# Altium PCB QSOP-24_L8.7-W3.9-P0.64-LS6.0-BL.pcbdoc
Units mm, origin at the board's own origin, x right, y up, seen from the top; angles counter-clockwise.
Board outline 21.81 x 19.48 mm, 2 copper layers (Top Layer, Bottom Layer), stack 0 mm thick; 1 components, 0 nets, 24 pads, 0 vias.
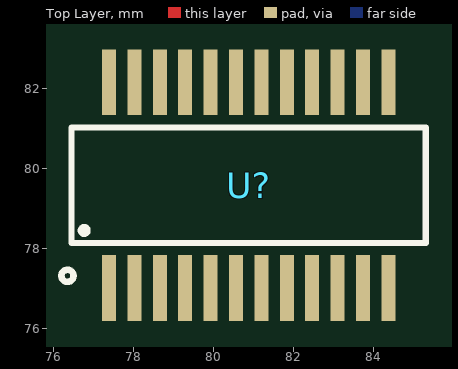
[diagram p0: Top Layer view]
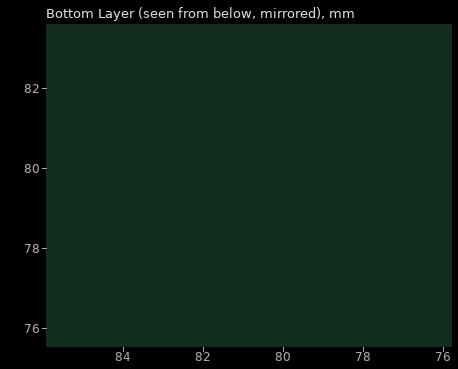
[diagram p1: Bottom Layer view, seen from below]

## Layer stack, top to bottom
Top Layer: signal copper (thickness not stored)
Bottom Layer: signal copper (thickness not stored)

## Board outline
91.659,69.85 69.85,69.85 69.85,89.33 91.659,89.33

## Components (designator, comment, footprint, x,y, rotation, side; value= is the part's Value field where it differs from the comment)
U? "" QSOP-24_L8.7-W3.9-P0.64-LS6.0-BL 80.883,79.59 r0 top

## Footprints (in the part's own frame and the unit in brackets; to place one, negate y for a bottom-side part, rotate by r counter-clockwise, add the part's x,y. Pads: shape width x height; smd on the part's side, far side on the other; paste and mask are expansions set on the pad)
QSOP-24_L8.7-W3.9-P0.64-LS6.0-BL [mm]
  rect 0.35x1.64 smd: 1(-3.492,-2.57) 2(-2.857,-2.57) 3(-2.222,-2.57) 4(-1.587,-2.57) 5(-0.953,-2.57) 6(-0.318,-2.57) 7(0.318,-2.57) 8(0.953,-2.57) 9(1.587,-2.57) 10(2.222,-2.57) 11(2.857,-2.57) 12(3.492,-2.57) 13(3.492,2.57) 14(2.857,2.57) 15(2.222,2.57) 16(1.587,2.57) 17(0.952,2.57) 18(0.317,2.57) 19(-0.318,2.57) 20(-0.953,2.57) 21(-1.588,2.57) 22(-2.223,2.57) 23(-2.858,2.57) 24(-3.492,2.57)
  silkscreen extent -4.68,-2.42 4.43,1.45

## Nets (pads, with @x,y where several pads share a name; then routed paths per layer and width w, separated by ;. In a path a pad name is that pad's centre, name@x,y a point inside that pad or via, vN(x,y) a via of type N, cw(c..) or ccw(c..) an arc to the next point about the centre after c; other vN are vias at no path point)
pads on no net: U?.1 U?.2 U?.3 U?.4 U?.5 U?.6 U?.7 U?.8 U?.9 U?.10 U?.11 U?.12 U?.13 U?.14 U?.15 U?.16 U?.17 U?.18 U?.19 U?.20 U?.21 U?.22 U?.23 U?.24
